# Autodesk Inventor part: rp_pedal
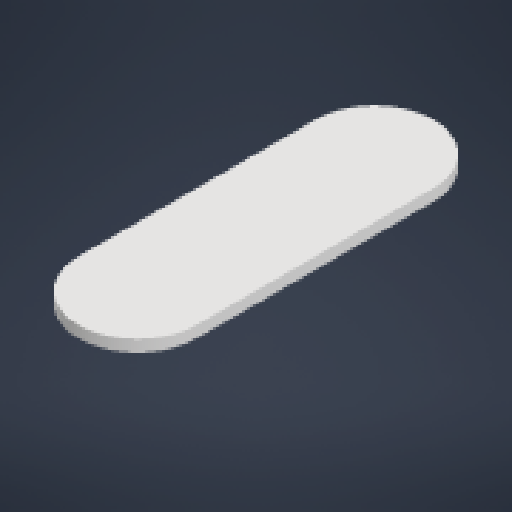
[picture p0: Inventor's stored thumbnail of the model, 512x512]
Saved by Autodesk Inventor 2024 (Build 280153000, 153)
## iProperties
Created: 2023-09
Part Number: rp_pedal
Material: Generic
Document SubType Name: Modeling
Designer: mammothbane
Density: 1 g/cm^3
Appearance: Default
Author: mammothbane
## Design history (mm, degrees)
sketch "Sketch1"
  geometry: L1 (0, 101.6)-(0, -101.6); L2 (-50.8, 101.6)-(-50.8, -101.6); L3 (50.8, -101.6)-(50.8, 101.6); A1 r 50.8 centre (0, 101.6) between (50.8, 101.6) and (-50.8, 101.6); A2 r 50.8 centre (0, -101.6) between (-50.8, -101.6) and (50.8, -101.6); 1 further point
  constraints: 8 end point, 4 point on circle, 4 tangent, 2 centre point, 1 midpoint, 1 parallel, 1 vertical
  dimensions: "d0" = 203.2 distance of L1.start L1.end; "d2" = 101.6 distance between parallel lines of L2 L3
extrude "Extrusion1" new body sketch "Sketch1" distance "d3" = 10; taper "d4" = 0 deg
sketch "Sketch2"
  geometry: L1 (-10, -30)-(10, -30); L2 (10, -30)-(10, 30); L3 (10, 30)-(-10, 30); L4 (-10, 30)-(-10, -30); L5 (-10, -30)-(10, 30); L6 (10, -30)-(-10, 30); 1 further point
  constraints: 12 end point, 2 midpoint, 2 parallel, 1 horizontal, 1 perpendicular
  dimensions: "d5" = 20 distance of L3.end L2.end; "d6" = 60 distance of L2.end L1.end
extrude "Extrusion2" join sketch "Sketch2" distance "d7" = 40; taper "d8" = 0 deg
body "Solid1"
